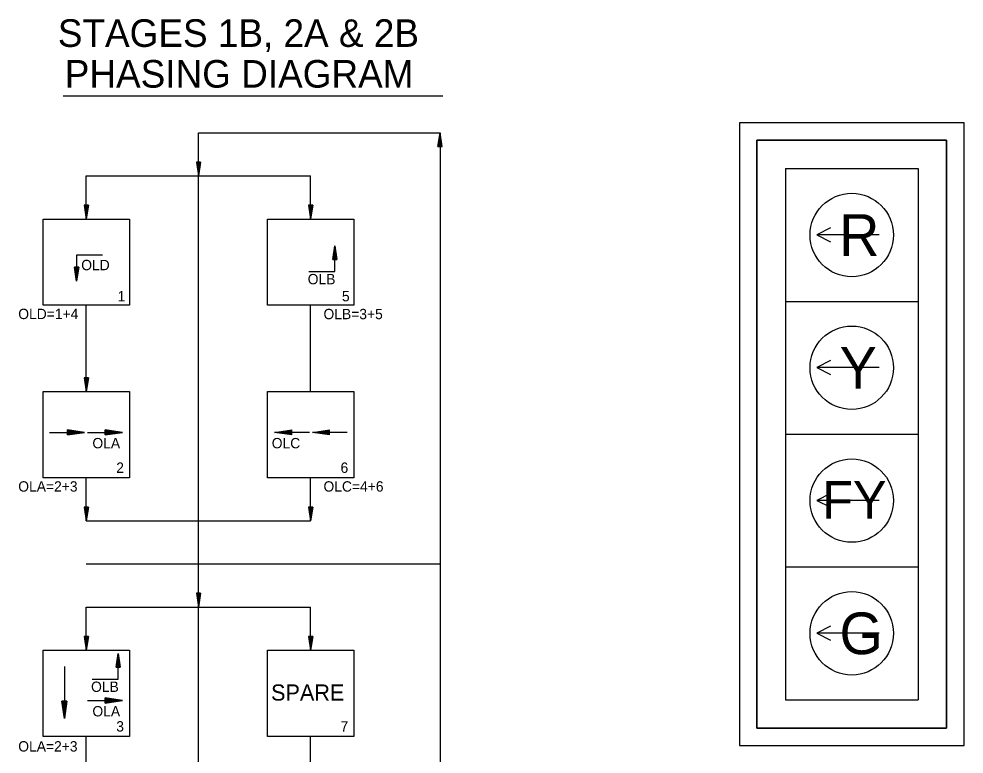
# Model space of a CAD drawing. Extents: x -218554 to 420030, y -566264 to -483460.
# Drawn here: x 418151 to 418341.5, y -565435.8 to -565287.5 of the extents above; entities that cross this region are included whole.
import ezdxf

# ---------------------------------------------------------------- set-up
doc = ezdxf.new("R2010")
doc.units = 0
for name, color, linetype in [('G-Border-Paper', 7, 'Continuous'), ('Level 57', 7, 'Continuous'), ('Level 61', 7, 'Continuous')]:
    doc.layers.add(name, color=color, linetype=linetype)

msp = doc.modelspace()

# ---------------------------------------------------------------- linework, layer by layer
at = {"layer": 'G-Border-Paper'}
for points in [[(418296.23, -565308.47), (418296.23, -565434.06), (418341.53, -565434.06), (418341.53, -565308.47), (418296.23, -565308.47)], [(418299.76, -565430.55), (418299.76, -565311.97), (418338.02, -565311.97), (418338.02, -565430.55), (418299.76, -565430.55)]]:
    msp.add_lwpolyline(points, dxfattribs=at)
at = {"layer": 'Level 57'}
for p, q in [((418159.94, -565303.03), (418236.46, -565303.03)), ((418187.2, -565493.1), (418187.2, -565310.48)), ((418187.2, -565310.48), (418235.9, -565310.48)), ((418235.48, -565313.26), (418235.9, -565310.48)), ((418235.9, -565310.48), (418235.9, -565493.1)), ((418236.32, -565313.26), (418235.9, -565310.48)), ((418235.55, -565313.26), (418235.9, -565310.94)), ((418235.62, -565313.26), (418235.9, -565311.42)), ((418235.69, -565313.26), (418235.9, -565311.89)), ((418235.77, -565313.26), (418235.9, -565312.36)), ((418236.25, -565313.26), (418235.9, -565310.94)), ((418236.18, -565313.26), (418235.9, -565311.42)), ((418236.11, -565313.26), (418235.9, -565311.89)), ((418236.04, -565313.26), (418235.9, -565312.36)), ((418235.48, -565313.26), (418236.32, -565313.26)), ((418235.84, -565313.26), (418235.9, -565312.82)), ((418235.97, -565313.26), (418235.9, -565312.82)), ((418186.79, -565316.39), (418187.2, -565319.17)), ((418187.62, -565316.39), (418186.79, -565316.39)), ((418186.86, -565316.39), (418187.2, -565318.71)), ((418186.93, -565316.39), (418187.2, -565318.23)), ((418187, -565316.39), (418187.2, -565317.77)), ((418187.07, -565316.39), (418187.2, -565317.3)), ((418187.14, -565316.39), (418187.2, -565316.83)), ((418187.62, -565316.39), (418187.2, -565319.17)), ((418187.34, -565316.39), (418187.2, -565317.3)), ((418187.48, -565316.39), (418187.2, -565318.23)), ((418187.55, -565316.39), (418187.2, -565318.71)), ((418187.41, -565316.39), (418187.2, -565317.77)), ((418187.27, -565316.39), (418187.2, -565316.83)), ((418164.59, -565327.87), (418164.59, -565319.17)), ((418164.59, -565319.17), (418209.81, -565319.17)), ((418209.81, -565327.87), (418209.81, -565319.17)), ((418164.18, -565325.09), (418164.59, -565327.87)), ((418165.01, -565325.09), (418164.18, -565325.09)), ((418164.25, -565325.09), (418164.59, -565327.41)), ((418164.32, -565325.09), (418164.59, -565326.93)), ((418164.39, -565325.09), (418164.59, -565326.46)), ((418164.46, -565325.09), (418164.59, -565325.99)), ((418164.53, -565325.09), (418164.59, -565325.53)), ((418165.01, -565325.09), (418164.59, -565327.87)), ((418164.73, -565325.09), (418164.59, -565325.99)), ((418164.87, -565325.09), (418164.59, -565326.93)), ((418164.94, -565325.09), (418164.59, -565327.41)), ((418164.8, -565325.09), (418164.59, -565326.46)), ((418164.66, -565325.09), (418164.59, -565325.53)), ((418209.4, -565325.09), (418209.81, -565327.87)), ((418210.23, -565325.09), (418209.4, -565325.09)), ((418209.47, -565325.09), (418209.81, -565327.41)), ((418209.54, -565325.09), (418209.81, -565326.93)), ((418209.61, -565325.09), (418209.81, -565326.46)), ((418209.68, -565325.09), (418209.81, -565325.99)), ((418209.75, -565325.09), (418209.81, -565325.53)), ((418210.23, -565325.09), (418209.81, -565327.87)), ((418209.95, -565325.09), (418209.81, -565325.99)), ((418210.09, -565325.09), (418209.81, -565326.93)), ((418210.16, -565325.09), (418209.81, -565327.41)), ((418210.02, -565325.09), (418209.81, -565326.46)), ((418209.88, -565325.09), (418209.81, -565325.53)), ((418214.25, -565336.05), (418214.66, -565333.27)), ((418214.66, -565338.48), (418214.66, -565333.27)), ((418214.66, -565333.27), (418215.08, -565336.05)), ((418167.85, -565335.16), (418162.63, -565335.16)), ((418162.63, -565335.16), (418162.63, -565340.38)), ((418214.66, -565333.73), (418214.31, -565336.05)), ((418214.39, -565336.05), (418214.66, -565334.21)), ((418214.66, -565334.67), (418214.46, -565336.05)), ((418214.53, -565336.05), (418214.66, -565335.15)), ((418215.01, -565336.05), (418214.66, -565333.73)), ((418214.66, -565334.21), (418214.94, -565336.05)), ((418214.87, -565336.05), (418214.66, -565334.67)), ((418214.66, -565335.15), (418214.8, -565336.05)), ((418214.25, -565336.05), (418215.08, -565336.05)), ((418214.66, -565335.61), (418214.6, -565336.05)), ((418214.73, -565336.05), (418214.66, -565335.61)), ((418162.63, -565340.38), (418162.22, -565337.6)), ((418163.05, -565337.6), (418162.22, -565337.6)), ((418162.29, -565337.6), (418162.63, -565339.92)), ((418162.63, -565339.44), (418162.36, -565337.6)), ((418162.43, -565337.6), (418162.63, -565338.98)), ((418162.63, -565338.5), (418162.5, -565337.6)), ((418162.57, -565337.6), (418162.63, -565338.04)), ((418162.63, -565338.04), (418162.7, -565337.6)), ((418162.77, -565337.6), (418162.63, -565338.5)), ((418162.63, -565338.98), (418162.84, -565337.6)), ((418162.91, -565337.6), (418162.63, -565339.44)), ((418162.63, -565339.92), (418162.98, -565337.6)), ((418163.05, -565337.6), (418162.63, -565340.38)), ((418209.44, -565338.48), (418214.66, -565338.48)), ((418164.59, -565362.66), (418164.59, -565345.26)), ((418209.81, -565362.66), (418209.81, -565345.26)), ((418164.18, -565359.87), (418164.59, -565362.66)), ((418165.01, -565359.87), (418164.18, -565359.87)), ((418164.25, -565359.87), (418164.59, -565362.19)), ((418164.32, -565359.87), (418164.59, -565361.71)), ((418164.39, -565359.87), (418164.59, -565361.25)), ((418164.46, -565359.87), (418164.59, -565360.78)), ((418164.53, -565359.87), (418164.59, -565360.31)), ((418165.01, -565359.87), (418164.59, -565362.66)), ((418164.73, -565359.87), (418164.59, -565360.78)), ((418164.87, -565359.87), (418164.59, -565361.71)), ((418164.94, -565359.87), (418164.59, -565362.19)), ((418164.8, -565359.87), (418164.59, -565361.25)), ((418164.66, -565359.87), (418164.59, -565360.31)), ((418157.2, -565370.9), (418164.25, -565370.9)), ((418164.25, -565370.9), (418160.78, -565370.38)), ((418160.78, -565371.42), (418160.78, -565370.38)), ((418160.78, -565370.46), (418163.67, -565370.9)), ((418163.07, -565370.9), (418160.78, -565370.55)), ((418160.78, -565370.64), (418162.5, -565370.9)), ((418161.91, -565370.9), (418160.78, -565370.73)), ((418160.78, -565370.82), (418161.33, -565370.9)), ((418161.33, -565370.9), (418160.78, -565370.98)), ((418160.78, -565371.07), (418161.91, -565370.9)), ((418162.5, -565370.9), (418160.78, -565371.16)), ((418160.78, -565371.24), (418163.07, -565370.9)), ((418163.67, -565370.9), (418160.78, -565371.33)), ((418160.78, -565371.42), (418164.25, -565370.9)), ((418164.83, -565370.9), (418171.88, -565370.9)), ((418171.88, -565370.9), (418168.4, -565370.38)), ((418168.4, -565371.42), (418168.4, -565370.38)), ((418168.4, -565370.46), (418171.29, -565370.9)), ((418170.7, -565370.9), (418168.4, -565370.55)), ((418168.4, -565370.64), (418170.12, -565370.9)), ((418169.53, -565370.9), (418168.4, -565370.73)), ((418168.4, -565370.82), (418168.95, -565370.9)), ((418168.95, -565370.9), (418168.4, -565370.98)), ((418168.4, -565371.07), (418169.53, -565370.9)), ((418170.12, -565370.9), (418168.4, -565371.16)), ((418168.4, -565371.24), (418170.7, -565370.9)), ((418171.29, -565370.9), (418168.4, -565371.33)), ((418168.4, -565371.42), (418171.88, -565370.9)), ((418202.53, -565370.9), (418206.01, -565370.38)), ((418209.58, -565370.9), (418202.53, -565370.9)), ((418206.01, -565371.42), (418202.53, -565370.9)), ((418206.01, -565370.46), (418203.11, -565370.9)), ((418203.11, -565370.9), (418206.01, -565371.33)), ((418203.71, -565370.9), (418206.01, -565370.55)), ((418206.01, -565371.24), (418203.71, -565370.9)), ((418206.01, -565370.64), (418204.29, -565370.9)), ((418204.29, -565370.9), (418206.01, -565371.16)), ((418204.88, -565370.9), (418206.01, -565370.73)), ((418206.01, -565371.07), (418204.88, -565370.9)), ((418206.01, -565370.82), (418205.46, -565370.9)), ((418205.46, -565370.9), (418206.01, -565370.98)), ((418206.01, -565371.42), (418206.01, -565370.38)), ((418210.15, -565370.9), (418213.63, -565370.38)), ((418217.2, -565370.9), (418210.15, -565370.9)), ((418213.63, -565371.42), (418210.15, -565370.9)), ((418213.63, -565370.46), (418210.73, -565370.9)), ((418210.73, -565370.9), (418213.63, -565371.33)), ((418211.33, -565370.9), (418213.63, -565370.55)), ((418213.63, -565371.24), (418211.33, -565370.9)), ((418213.63, -565370.64), (418211.91, -565370.9)), ((418211.91, -565370.9), (418213.63, -565371.16)), ((418212.5, -565370.9), (418213.63, -565370.73)), ((418213.63, -565371.07), (418212.5, -565370.9)), ((418213.63, -565370.82), (418213.08, -565370.9)), ((418213.08, -565370.9), (418213.63, -565370.98)), ((418213.63, -565371.42), (418213.63, -565370.38)), ((418164.59, -565388.74), (418164.59, -565380.05)), ((418209.81, -565388.74), (418209.81, -565380.05)), ((418209.81, -565388.74), (418209.81, -565380.05)), ((418164.18, -565385.96), (418164.59, -565388.74)), ((418165.01, -565385.96), (418164.18, -565385.96)), ((418164.25, -565385.96), (418164.59, -565388.28)), ((418164.32, -565385.96), (418164.59, -565387.8)), ((418164.39, -565385.96), (418164.59, -565387.34)), ((418164.46, -565385.96), (418164.59, -565386.86)), ((418164.53, -565385.96), (418164.59, -565386.4)), ((418165.01, -565385.96), (418164.59, -565388.74)), ((418164.73, -565385.96), (418164.59, -565386.86)), ((418164.87, -565385.96), (418164.59, -565387.8)), ((418164.94, -565385.96), (418164.59, -565388.28)), ((418164.8, -565385.96), (418164.59, -565387.34)), ((418164.66, -565385.96), (418164.59, -565386.4)), ((418209.4, -565385.96), (418209.81, -565388.74)), ((418210.23, -565385.96), (418209.4, -565385.96)), ((418209.4, -565385.96), (418209.81, -565388.74)), ((418210.23, -565385.96), (418209.4, -565385.96)), ((418209.47, -565385.96), (418209.81, -565388.28)), ((418209.47, -565385.96), (418209.81, -565388.28)), ((418209.54, -565385.96), (418209.81, -565387.8)), ((418209.54, -565385.96), (418209.81, -565387.8)), ((418209.61, -565385.96), (418209.81, -565387.34)), ((418209.61, -565385.96), (418209.81, -565387.34)), ((418209.68, -565385.96), (418209.81, -565386.86)), ((418209.68, -565385.96), (418209.81, -565386.86)), ((418209.75, -565385.96), (418209.81, -565386.4)), ((418209.75, -565385.96), (418209.81, -565386.4)), ((418210.23, -565385.96), (418209.81, -565388.74)), ((418209.95, -565385.96), (418209.81, -565386.86)), ((418210.09, -565385.96), (418209.81, -565387.8)), ((418210.16, -565385.96), (418209.81, -565388.28)), ((418210.02, -565385.96), (418209.81, -565387.34)), ((418209.88, -565385.96), (418209.81, -565386.4)), ((418210.23, -565385.96), (418209.81, -565388.74)), ((418209.95, -565385.96), (418209.81, -565386.86)), ((418210.09, -565385.96), (418209.81, -565387.8)), ((418210.16, -565385.96), (418209.81, -565388.28)), ((418210.02, -565385.96), (418209.81, -565387.34)), ((418209.88, -565385.96), (418209.81, -565386.4)), ((418164.59, -565388.74), (418209.81, -565388.74)), ((418164.59, -565397.44), (418235.9, -565397.44)), ((418186.79, -565403.35), (418187.2, -565406.14)), ((418187.62, -565403.35), (418186.79, -565403.35)), ((418186.86, -565403.35), (418187.2, -565405.67)), ((418186.93, -565403.35), (418187.2, -565405.19)), ((418187, -565403.35), (418187.2, -565404.73)), ((418187.07, -565403.35), (418187.2, -565404.26)), ((418187.14, -565403.35), (418187.2, -565403.79)), ((418187.62, -565403.35), (418187.2, -565406.14)), ((418187.34, -565403.35), (418187.2, -565404.26)), ((418187.48, -565403.35), (418187.2, -565405.19)), ((418187.55, -565403.35), (418187.2, -565405.67)), ((418187.41, -565403.35), (418187.2, -565404.73)), ((418187.27, -565403.35), (418187.2, -565403.79)), ((418164.59, -565406.14), (418209.81, -565406.14)), ((418164.59, -565414.83), (418164.59, -565406.14)), ((418209.81, -565414.83), (418209.81, -565406.14)), ((418164.18, -565412.05), (418164.59, -565414.83)), ((418165.01, -565412.05), (418164.18, -565412.05)), ((418164.25, -565412.05), (418164.59, -565414.37)), ((418164.32, -565412.05), (418164.59, -565413.89)), ((418164.39, -565412.05), (418164.59, -565413.42)), ((418164.46, -565412.05), (418164.59, -565412.95)), ((418164.53, -565412.05), (418164.59, -565412.49)), ((418165.01, -565412.05), (418164.59, -565414.83)), ((418164.73, -565412.05), (418164.59, -565412.95)), ((418164.87, -565412.05), (418164.59, -565413.89)), ((418164.94, -565412.05), (418164.59, -565414.37)), ((418164.8, -565412.05), (418164.59, -565413.42)), ((418164.66, -565412.05), (418164.59, -565412.49)), ((418209.4, -565412.05), (418209.81, -565414.83)), ((418210.23, -565412.05), (418209.4, -565412.05)), ((418209.47, -565412.05), (418209.81, -565414.37)), ((418209.54, -565412.05), (418209.81, -565413.89)), ((418209.61, -565412.05), (418209.81, -565413.42)), ((418209.68, -565412.05), (418209.81, -565412.95)), ((418209.75, -565412.05), (418209.81, -565412.49)), ((418210.23, -565412.05), (418209.81, -565414.83)), ((418209.95, -565412.05), (418209.81, -565412.95)), ((418210.09, -565412.05), (418209.81, -565413.89)), ((418210.16, -565412.05), (418209.81, -565414.37)), ((418210.02, -565412.05), (418209.81, -565413.42)), ((418209.88, -565412.05), (418209.81, -565412.49)), ((418170.58, -565418.26), (418171, -565415.47)), ((418171, -565415.94), (418170.65, -565418.26)), ((418170.72, -565418.26), (418171, -565416.42)), ((418171, -565416.88), (418170.79, -565418.26)), ((418171, -565420.69), (418171, -565415.47)), ((418171, -565415.47), (418171.42, -565418.26)), ((418171.35, -565418.26), (418171, -565415.94)), ((418171, -565416.42), (418171.28, -565418.26)), ((418171.21, -565418.26), (418171, -565416.88)), ((418160.17, -565418.13), (418160.17, -565428.57)), ((418170.58, -565418.26), (418171.42, -565418.26)), ((418170.86, -565418.26), (418171, -565417.35)), ((418171, -565417.82), (418170.93, -565418.26)), ((418171, -565417.35), (418171.14, -565418.26)), ((418171.06, -565418.26), (418171, -565417.82)), ((418165.78, -565420.69), (418171, -565420.69)), ((418171.88, -565424.97), (418168.4, -565424.45)), ((418168.4, -565425.49), (418168.4, -565424.45)), ((418168.4, -565424.54), (418171.29, -565424.97)), ((418170.7, -565424.97), (418168.4, -565424.63)), ((418168.4, -565424.71), (418170.12, -565424.97)), ((418160.17, -565428.57), (418159.65, -565425.09)), ((418160.69, -565425.09), (418159.65, -565425.09)), ((418159.74, -565425.09), (418160.17, -565427.99)), ((418160.17, -565427.39), (418159.83, -565425.09)), ((418159.91, -565425.09), (418160.17, -565426.81)), ((418160.17, -565426.22), (418160, -565425.09)), ((418160.09, -565425.09), (418160.17, -565425.64)), ((418160.17, -565425.64), (418160.25, -565425.09)), ((418160.34, -565425.09), (418160.17, -565426.22)), ((418160.17, -565426.81), (418160.43, -565425.09)), ((418160.52, -565425.09), (418160.17, -565427.39)), ((418160.17, -565427.99), (418160.61, -565425.09)), ((418160.69, -565425.09), (418160.17, -565428.57)), ((418164.83, -565424.97), (418171.88, -565424.97)), ((418169.53, -565424.97), (418168.4, -565424.8)), ((418168.4, -565424.89), (418168.95, -565424.97)), ((418168.95, -565424.97), (418168.4, -565425.05)), ((418168.4, -565425.14), (418169.53, -565424.97)), ((418170.12, -565424.97), (418168.4, -565425.23)), ((418168.4, -565425.32), (418170.7, -565424.97)), ((418171.29, -565424.97), (418168.4, -565425.41)), ((418168.4, -565425.49), (418171.88, -565424.97)), ((418164.59, -565449.62), (418164.59, -565432.22)), ((418209.81, -565449.62), (418209.81, -565432.22))]:
    msp.add_line(p, q, dxfattribs=at)
for points in [[(418155.9, -565327.87), (418173.29, -565327.87), (418173.29, -565345.26), (418155.9, -565345.26)], [(418201.12, -565327.87), (418218.51, -565327.87), (418218.51, -565345.26), (418201.12, -565345.26)], [(418155.9, -565362.66), (418173.29, -565362.66), (418173.29, -565380.05), (418155.9, -565380.05)], [(418201.12, -565362.66), (418218.51, -565362.66), (418218.51, -565380.05), (418201.12, -565380.05)], [(418155.9, -565414.83), (418173.29, -565414.83), (418173.29, -565432.22), (418155.9, -565432.22)], [(418201.12, -565414.83), (418218.51, -565414.83), (418218.51, -565432.22), (418201.12, -565432.22)]]:
    msp.add_lwpolyline(points, close=True, dxfattribs=at)
at = {"layer": 'Level 61'}
for p, q in [((418305.5, -565317.71), (418332.28, -565317.71)), ((418305.5, -565317.71), (418305.5, -565344.48)), ((418332.28, -565317.71), (418332.28, -565344.48)), ((418324.44, -565331.06), (418311.82, -565331.06)), ((418305.5, -565344.48), (418332.28, -565344.48)), ((418305.5, -565344.48), (418305.5, -565371.26)), ((418332.28, -565344.48), (418332.28, -565371.26)), ((418324.44, -565357.83), (418311.82, -565357.83)), ((418305.5, -565371.26), (418332.28, -565371.26)), ((418305.5, -565371.26), (418305.5, -565398.04)), ((418332.28, -565371.26), (418332.28, -565398.04)), ((418324.44, -565384.61), (418311.82, -565384.61)), ((418305.5, -565398.04), (418332.28, -565398.04)), ((418305.5, -565398.04), (418305.5, -565424.81)), ((418332.28, -565398.04), (418332.28, -565424.81)), ((418324.44, -565411.39), (418311.82, -565411.39)), ((418305.5, -565424.81), (418332.28, -565424.81))]:
    msp.add_line(p, q, dxfattribs=at)
msp.add_lwpolyline([(418338.02, -565311.97), (418299.76, -565311.97), (418299.76, -565430.55), (418338.02, -565430.55)], close=True, dxfattribs=at)
for points in [[(418314.62, -565329.66), (418311.82, -565331.06), (418314.62, -565332.46)], [(418314.62, -565356.43), (418311.82, -565357.83), (418314.62, -565359.24)], [(418314.62, -565383.21), (418311.82, -565384.61), (418314.62, -565386.01)], [(418314.62, -565409.99), (418311.82, -565411.39), (418314.62, -565412.79)]]:
    msp.add_lwpolyline(points, dxfattribs=at)
for centre in [(418318.89, -565331.09), (418318.89, -565357.87), (418318.89, -565384.65), (418318.89, -565411.42)]:
    msp.add_circle(centre, 8.41, dxfattribs=at)

# ---------------------------------------------------------------- texts
at = {"layer": 'Level 57'}
for s, height, p in [('STAGES 1B, 2A & 2B', 5.5655, (418158.85, -565293.15)), ('PHASING DIAGRAM', 5.5655, (418160.24, -565301.37)), ('OLD', 2.087, (418163.56, -565338.19)), ('OLB', 2.087, (418209.22, -565341.03)), ('1', 2.09, (418170.9, -565344.47)), ('5', 2.09, (418216.12, -565344.47)), ('OLD=1+4', 2.087, (418150.87, -565348.05)), ('OLB=3+5', 2.087, (418212.4, -565348.07)), ('OLA', 2.087, (418165.82, -565374.11)), ('OLC', 2.087, (418201.97, -565374.11)), ('2', 2.09, (418170.62, -565379.06)), ('6', 2.09, (418215.84, -565379.06)), ('OLA=2+3', 2.087, (418150.87, -565382.84)), ('OLC=4+6', 2.087, (418212.4, -565382.84)), ('OLB', 2.087, (418165.55, -565423.24)), ('SPARE', 3.261, (418201.83, -565424.99)), ('OLA', 2.087, (418165.82, -565428.18)), ('3', 2.09, (418170.62, -565431.23)), ('7', 2.09, (418215.84, -565431.23)), ('OLA=2+3', 2.087, (418150.87, -565435.26))]:
    msp.add_text(s, height=height, dxfattribs=at).set_placement(p)
at = {"layer": 'Level 61'}
for s, height, p in [('R', 8.41, (418316.34, -565335.3)), ('Y', 8.41, (418316.44, -565362.08)), ('FY', 7.605, (418312.91, -565388.31)), ('G', 8.41, (418316.42, -565415.63))]:
    msp.add_text(s, height=height, dxfattribs=at).set_placement(p)

doc.saveas('drawing.dxf')
